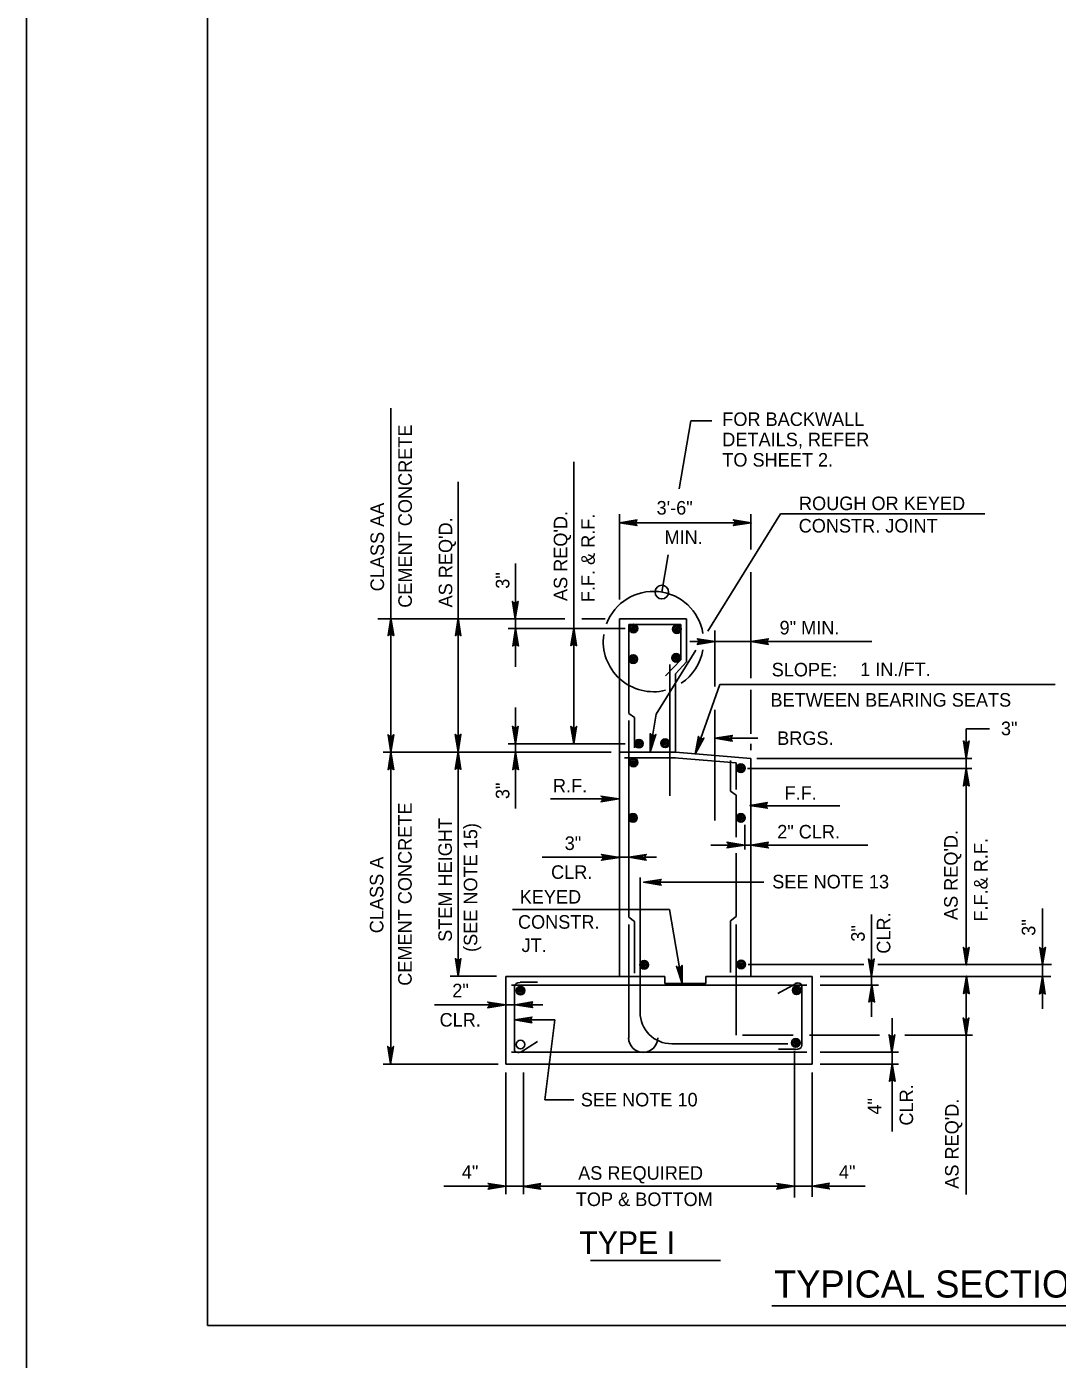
# Model space of a CAD drawing. Extents: x 235 to 2276, y 116 to 1308.
# Drawn here: x 579.4 to 807.5, y 717.9 to 1012.9 of the extents above; entities that cross this region are included whole.
import ezdxf

# ---------------------------------------------------------------- set-up
doc = ezdxf.new("R2010")
doc.units = 0
doc.layers.add('1', color=7, linetype='Continuous')
doc.layers.add('PLT-BNDY', color=7, linetype='Continuous')

msp = doc.modelspace()

# ---------------------------------------------------------------- linework, layer by layer
at = {"layer": '1'}
for p, q in [((619.42, 725.41), (619.42, 1289.41)), ((660.02, 879.66), (660.02, 928.45)), ((723.87, 910.62), (726.42, 925.68)), ((726.42, 925.68), (731.07, 925.68)), ((700.51, 916.6), (700.51, 889.19)), ((674.93, 879.66), (674.93, 912.13)), ((710.65, 886.09), (710.65, 904.97)), ((710.65, 903.1), (739.71, 903.1)), ((746.27, 905.11), (730.15, 879.09)), ((739.71, 897.2), (739.71, 904.97)), ((746.27, 905.11), (791.46, 905.11)), ((687.58, 881.85), (687.58, 894.1)), ((720, 887.75), (721.39, 895.99)), ((739.71, 868.72), (739.71, 892.15)), ((700.51, 889.19), (700.51, 877.63)), ((698.53, 881.85), (657.12, 881.85)), ((660.02, 852.32), (660.02, 881.85)), ((674.93, 802.76), (674.93, 881.85)), ((711.9, 879.66), (685.96, 879.66)), ((687.58, 881.85), (687.58, 871.22)), ((700.51, 879.66), (700.51, 854.19)), ((707.44, 881.85), (702.3, 881.85)), ((710.65, 802.63), (710.65, 881.85)), ((710.65, 881.85), (725.49, 881.85)), ((712.68, 860.91), (712.68, 880.6)), ((712.68, 880.6), (724.24, 880.6)), ((724.24, 872.79), (724.24, 880.6)), ((725.49, 872.32), (725.49, 881.85)), ((731.74, 866.88), (731.74, 879.23)), ((726.22, 876.8), (766.46, 876.8)), ((727.52, 874.86), (718.77, 860.76)), ((720.81, 869.19), (724.24, 872.79)), ((721.74, 842.63), (721.74, 871.69)), ((722.99, 869.66), (725.49, 872.32)), ((722.99, 852.32), (722.99, 869.66)), ((732.84, 867.31), (807.06, 867.31)), ((739.71, 865.13), (739.71, 866.1)), ((739.71, 856.4), (739.71, 865.13)), ((687.58, 854.19), (687.58, 862.21)), ((731.74, 837.16), (731.74, 861.72)), ((713.93, 859.97), (712.68, 860.91)), ((712.68, 815.76), (712.68, 859.35)), ((713.93, 853.26), (713.93, 859.97)), ((717.37, 852.32), (718.77, 860.76)), ((787.37, 848.72), (787.37, 857.45)), ((787.37, 857.45), (792.5, 857.45)), ((711.9, 854.19), (685.96, 854.19)), ((687.58, 854.19), (687.58, 839.87)), ((731.74, 855.38), (741.27, 855.38)), ((739.71, 852.79), (739.71, 854.18)), ((680.34, 852.32), (658.31, 852.32)), ((660.02, 852.32), (660.02, 783.26)), ((708.77, 852.32), (680.34, 852.32)), ((710.65, 852.32), (722.99, 852.32)), ((711.74, 851.07), (722.99, 851.07)), ((722.84, 851.07), (736.43, 849.97)), ((722.99, 852.32), (739.71, 850.91)), ((735.18, 843.72), (735.18, 850.44)), ((736.43, 844.04), (736.43, 849.97)), ((739.71, 802.63), (739.71, 850.91)), ((741, 850.91), (788.62, 850.91)), ((738.93, 848.72), (759.4, 848.72)), ((759.4, 848.72), (788.62, 848.72)), ((787.37, 805.29), (787.37, 848.72)), ((735.18, 843.72), (736.43, 842.79)), ((695.34, 842.01), (710.65, 842.01)), ((736.43, 833.52), (736.43, 842.79)), ((739.71, 840.44), (759.4, 840.44)), ((738.39, 830.75), (738.39, 836.22)), ((693.5, 829.04), (710.65, 829.04)), ((710.65, 829.04), (718.83, 829.04)), ((738.39, 831.74), (730.88, 831.74)), ((736.43, 815.91), (736.43, 829.99)), ((739.71, 831.74), (738.39, 831.74)), ((765.61, 831.74), (739.71, 831.74)), ((715.18, 794.77), (715.18, 824.61)), ((742.55, 823.54), (715.98, 823.54)), ((721.7, 817.47), (686.94, 817.47)), ((724.47, 801.1), (721.7, 817.47)), ((804.24, 805.29), (804.24, 817.73)), ((713.93, 814.82), (712.68, 815.76)), ((713.93, 803.41), (713.93, 814.82)), ((735.18, 814.97), (736.43, 815.91)), ((735.18, 803.57), (735.18, 814.97)), ((766.43, 802.63), (766.43, 816.36)), ((712.68, 789.04), (712.68, 814.19)), ((736.43, 789.66), (736.43, 814.19)), ((673.19, 802.76), (683.38, 802.76)), ((685.49, 783.26), (685.49, 802.63)), ((685.49, 802.63), (720.65, 802.63)), ((720.65, 802.63), (720.65, 801.1)), ((729.71, 802.63), (753.31, 802.63)), ((729.71, 802.63), (729.71, 801.1)), ((739.09, 805.29), (764.71, 805.29)), ((753.31, 783.26), (753.31, 802.63)), ((755.01, 802.63), (806.12, 802.63)), ((766.43, 793.72), (766.43, 802.63)), ((767.84, 805.29), (806.27, 805.29)), ((787.37, 789.66), (787.37, 802.63)), ((804.22, 795.48), (804.22, 805.29)), ((686.74, 800.76), (752.06, 800.76)), ((687.37, 800.6), (687.37, 786.38)), ((692.52, 801.38), (688.62, 801.38)), ((720.65, 801.1), (729.71, 801.1)), ((749.56, 801.07), (745.65, 798.88)), ((750.96, 787.32), (750.96, 800.76)), ((755.01, 800.76), (767.99, 800.76)), ((669.66, 796.39), (685.49, 796.39)), ((685.49, 796.39), (693.68, 796.39)), ((687.37, 793.07), (696.31, 793.07)), ((696.31, 793.07), (694.09, 775.33)), ((770.96, 785.91), (770.96, 793.41)), ((688.77, 785.91), (692.52, 788.26)), ((747.86, 787.77), (722.18, 787.77)), ((737.84, 789.66), (749.08, 789.66)), ((752.68, 789.66), (759.4, 789.66)), ((759.4, 789.66), (768.15, 789.66)), ((773.77, 789.66), (788.77, 789.66)), ((787.37, 754.43), (787.37, 789.66)), ((686.74, 785.91), (752.06, 785.91)), ((745.81, 786.54), (749.56, 786.54)), ((749.4, 786.22), (749.4, 753.72)), ((755.01, 785.91), (772.37, 785.91)), ((770.96, 768.33), (770.96, 785.91)), ((680.34, 783.26), (658.31, 783.26)), ((683.77, 783.26), (680.34, 783.26)), ((685.49, 783.26), (753.31, 783.26)), ((755.01, 783.26), (772.37, 783.26)), ((685.49, 781.38), (685.49, 776.38)), ((689.4, 781.38), (689.4, 754.51)), ((753.31, 781.38), (753.31, 776.38)), ((685.49, 776.38), (685.49, 754.51)), ((753.31, 776.38), (753.31, 753.88)), ((694.09, 775.33), (700.49, 775.33)), ((689.4, 756.22), (671.74, 756.22)), ((689.4, 756.22), (749.4, 756.22)), ((749.4, 756.22), (765.04, 756.22)), ((704.23, 739.79), (732.98, 739.79)), ((744.38, 729.75), (916.51, 729.75)), ((1405.42, 725.41), (619.42, 725.41))]:
    msp.add_line(p, q, dxfattribs=at)
for points in [[(714.4, 902.6), (714.27, 902.85), (710.65, 903.1), (714.4, 902.6), (714.52, 902.47), (710.65, 903.1), (714.27, 903.22), (714.4, 903.6), (710.65, 903.1), (714.52, 903.72), (714.4, 903.6)], [(736.05, 903.58), (736.18, 903.33), (739.8, 903.08), (736.05, 903.58), (735.8, 903.71), (739.8, 903.08), (736.18, 902.96), (736.05, 902.71), (739.8, 903.08), (735.8, 902.46), (736.05, 902.71)], [(688.07, 885.56), (687.82, 885.31), (687.57, 881.81), (688.07, 885.56), (688.19, 885.69), (687.57, 881.81), (687.44, 885.31), (687.19, 885.44), (687.57, 881.81), (686.94, 885.69), (687.19, 885.44)], [(659.52, 878.25), (659.77, 878.38), (660.02, 882), (659.52, 878.25), (659.4, 878.13), (660.02, 882), (660.15, 878.38), (660.52, 878.25), (660.02, 882), (660.65, 878.13), (660.52, 878.25)], [(674.42, 878.22), (674.67, 878.34), (674.92, 881.97), (674.42, 878.22), (674.3, 878.09), (674.92, 881.97), (675.05, 878.34), (675.42, 878.22), (674.92, 881.97), (675.55, 878.09), (675.42, 878.22)], [(687.13, 875.91), (687.38, 876.04), (687.63, 879.66), (687.13, 875.91), (687, 875.79), (687.63, 879.66), (687.75, 876.04), (688.13, 875.91), (687.63, 879.66), (688.25, 875.79), (688.13, 875.91)], [(700, 876.02), (700.25, 876.15), (700.5, 879.77), (700, 876.02), (699.87, 875.9), (700.5, 879.77), (700.62, 876.15), (701, 876.02), (700.5, 879.77), (701.12, 875.9), (701, 876.02)], [(728.08, 877.29), (728.21, 877.04), (731.83, 876.79), (728.08, 877.29), (727.83, 877.41), (731.83, 876.79), (728.21, 876.66), (728.08, 876.41), (731.83, 876.79), (727.83, 876.16), (728.08, 876.41)], [(743.46, 876.3), (743.34, 876.55), (739.71, 876.8), (743.46, 876.3), (743.59, 876.18), (739.71, 876.8), (743.34, 876.93), (743.46, 877.3), (739.71, 876.8), (743.59, 877.43), (743.46, 877.3)], [(732.84, 867.31), (727.37, 851.85)], [(660.52, 856.07), (660.27, 855.82), (660.02, 852.32), (660.52, 856.07), (660.65, 856.19), (660.02, 852.32), (659.9, 855.82), (659.65, 855.94), (660.02, 852.32), (659.4, 856.19), (659.65, 855.94)], [(675.4, 856.12), (675.15, 855.87), (674.9, 852.37), (675.4, 856.12), (675.52, 856.25), (674.9, 852.37), (674.77, 855.87), (674.52, 856), (674.9, 852.37), (674.27, 856.25), (674.52, 856)], [(688.08, 857.94), (687.83, 857.69), (687.58, 854.19), (688.08, 857.94), (688.2, 858.07), (687.58, 854.19), (687.45, 857.69), (687.2, 857.82), (687.58, 854.19), (686.95, 858.07), (687.2, 857.82)], [(701.01, 857.9), (700.76, 857.65), (700.51, 854.15), (701.01, 857.9), (701.14, 858.03), (700.51, 854.15), (700.39, 857.65), (700.14, 857.78), (700.51, 854.15), (699.89, 858.03), (700.14, 857.78)], [(718.5, 856.07), (718.2, 855.98), (717.41, 852.42), (718.5, 856.07), (718.69, 856.23), (717.41, 852.42), (717.83, 856.04), (717.58, 856.21), (717.41, 852.42), (717.44, 856.44), (717.58, 856.21)], [(729.08, 855.3), (728.78, 855.26), (727.37, 851.9), (729.08, 855.3), (729.3, 855.43), (727.37, 851.9), (728.42, 855.38), (728.21, 855.6), (727.37, 851.9), (728.1, 855.85), (728.21, 855.6)], [(735.48, 854.89), (735.35, 855.14), (731.73, 855.39), (735.48, 854.89), (735.6, 854.77), (731.73, 855.39), (735.35, 855.52), (735.48, 855.89), (731.73, 855.39), (735.6, 856.02), (735.48, 855.89)], [(787.87, 854.66), (787.62, 854.41), (787.37, 850.91), (787.87, 854.66), (787.99, 854.79), (787.37, 850.91), (787.24, 854.41), (786.99, 854.54), (787.37, 850.91), (786.74, 854.79), (786.99, 854.54)], [(659.52, 848.57), (659.77, 848.69), (660.02, 852.32), (659.52, 848.57), (659.4, 848.44), (660.02, 852.32), (660.15, 848.69), (660.52, 848.57), (660.02, 852.32), (660.65, 848.44), (660.52, 848.57)], [(674.4, 848.62), (674.65, 848.75), (674.9, 852.37), (674.4, 848.62), (674.27, 848.5), (674.9, 852.37), (675.02, 848.75), (675.4, 848.62), (674.9, 852.37), (675.52, 848.5), (675.4, 848.62)], [(687.13, 848.57), (687.38, 848.69), (687.63, 852.32), (687.13, 848.57), (687, 848.44), (687.63, 852.32), (687.75, 848.69), (688.13, 848.57), (687.63, 852.32), (688.25, 848.44), (688.13, 848.57)], [(786.87, 844.97), (787.12, 845.1), (787.37, 848.72), (786.87, 844.97), (786.74, 844.85), (787.37, 848.72), (787.49, 845.1), (787.87, 844.97), (787.37, 848.72), (787.99, 844.85), (787.87, 844.97)], [(706.76, 842.49), (706.88, 842.24), (710.51, 841.99), (706.76, 842.49), (706.51, 842.61), (710.51, 841.99), (706.88, 841.86), (706.76, 841.61), (710.51, 841.99), (706.51, 841.36), (706.76, 841.61)], [(743.25, 840.03), (743.13, 840.28), (739.5, 840.53), (743.25, 840.03), (743.38, 839.9), (739.5, 840.53), (743.13, 840.65), (743.25, 841.03), (739.5, 840.53), (743.38, 841.15), (743.25, 841.03)], [(734.64, 832.24), (734.76, 831.99), (738.39, 831.74), (734.64, 832.24), (734.39, 832.37), (738.39, 831.74), (734.76, 831.62), (734.64, 831.37), (738.39, 831.74), (734.39, 831.12), (734.64, 831.37)], [(743.46, 831.24), (743.34, 831.49), (739.71, 831.74), (743.46, 831.24), (743.59, 831.12), (739.71, 831.74), (743.34, 831.87), (743.46, 832.24), (739.71, 831.74), (743.59, 832.37), (743.46, 832.24)], [(706.88, 829.53), (707, 829.28), (710.63, 829.03), (706.88, 829.53), (706.63, 829.66), (710.63, 829.03), (707, 828.91), (706.88, 828.66), (710.63, 829.03), (706.63, 828.41), (706.88, 828.66)], [(716.42, 828.55), (716.3, 828.8), (712.67, 829.05), (716.42, 828.55), (716.55, 828.43), (712.67, 829.05), (716.3, 829.18), (716.42, 829.55), (712.67, 829.05), (716.55, 829.68), (716.42, 829.55)], [(719.73, 823.04), (719.61, 823.29), (715.98, 823.54), (719.73, 823.04), (719.86, 822.91), (715.98, 823.54), (719.61, 823.66), (719.73, 824.04), (715.98, 823.54), (719.86, 824.16), (719.73, 824.04)], [(787.88, 808.98), (787.63, 808.73), (787.38, 805.23), (787.88, 808.98), (788, 809.1), (787.38, 805.23), (787.25, 808.73), (787, 808.85), (787.38, 805.23), (786.75, 809.1), (787, 808.85)], [(804.76, 808.97), (804.51, 808.72), (804.26, 805.22), (804.76, 808.97), (804.89, 809.09), (804.26, 805.22), (804.14, 808.72), (803.89, 808.84), (804.26, 805.22), (803.64, 809.09), (803.89, 808.84)], [(675.43, 806.51), (675.18, 806.26), (674.93, 802.76), (675.43, 806.51), (675.55, 806.64), (674.93, 802.76), (674.8, 806.26), (674.55, 806.39), (674.93, 802.76), (674.3, 806.64), (674.55, 806.39)], [(766.87, 806.42), (766.62, 806.17), (766.37, 802.67), (766.87, 806.42), (767, 806.54), (766.37, 802.67), (766.25, 806.17), (766, 806.29), (766.37, 802.67), (765.75, 806.54), (766, 806.29)], [(724.36, 804.91), (724.11, 804.73), (724.47, 801.1), (724.36, 804.91), (724.49, 805.13), (724.47, 801.1), (723.74, 804.67), (723.45, 804.76), (724.47, 801.1), (723.24, 804.93), (723.45, 804.76)], [(786.9, 799), (787.15, 799.13), (787.4, 802.75), (786.9, 799), (786.78, 798.88), (787.4, 802.75), (787.53, 799.13), (787.9, 799), (787.4, 802.75), (788.03, 798.88), (787.9, 799)], [(803.74, 798.88), (803.99, 799.01), (804.24, 802.63), (803.74, 798.88), (803.62, 798.76), (804.24, 802.63), (804.37, 799.01), (804.74, 798.88), (804.24, 802.63), (804.87, 798.76), (804.74, 798.88)], [(765.95, 797.13), (766.2, 797.25), (766.45, 800.88), (765.95, 797.13), (765.83, 797), (766.45, 800.88), (766.58, 797.25), (766.95, 797.13), (766.45, 800.88), (767.08, 797), (766.95, 797.13)], [(681.72, 796.89), (681.85, 796.64), (685.47, 796.39), (681.72, 796.89), (681.47, 797.01), (685.47, 796.39), (681.85, 796.26), (681.72, 796.01), (685.47, 796.39), (681.47, 795.76), (681.72, 796.01)], [(691.27, 795.91), (691.14, 796.16), (687.52, 796.41), (691.27, 795.91), (691.39, 795.78), (687.52, 796.41), (691.14, 796.53), (691.27, 796.91), (687.52, 796.41), (691.39, 797.03), (691.27, 796.91)], [(691.12, 792.57), (690.99, 792.82), (687.37, 793.07), (691.12, 792.57), (691.24, 792.44), (687.37, 793.07), (690.99, 793.19), (691.12, 793.57), (687.37, 793.07), (691.24, 793.69), (691.12, 793.57)], [(787.83, 793.37), (787.58, 793.12), (787.33, 789.62), (787.83, 793.37), (787.95, 793.49), (787.33, 789.62), (787.2, 793.12), (786.95, 793.24), (787.33, 789.62), (786.7, 793.49), (786.95, 793.24)], [(771.43, 789.62), (771.18, 789.37), (770.93, 785.87), (771.43, 789.62), (771.55, 789.75), (770.93, 785.87), (770.8, 789.37), (770.55, 789.5), (770.93, 785.87), (770.3, 789.75), (770.55, 789.5)], [(660.48, 787.05), (660.23, 786.8), (659.98, 783.3), (660.48, 787.05), (660.6, 787.17), (659.98, 783.3), (659.85, 786.8), (659.6, 786.92), (659.98, 783.3), (659.35, 787.17), (659.6, 786.92)], [(770.49, 779.6), (770.74, 779.73), (770.99, 783.35), (770.49, 779.6), (770.37, 779.48), (770.99, 783.35), (771.12, 779.73), (771.49, 779.6), (770.99, 783.35), (771.62, 779.48), (771.49, 779.6)], [(681.79, 756.72), (681.92, 756.47), (685.54, 756.22), (681.79, 756.72), (681.54, 756.85), (685.54, 756.22), (681.92, 756.1), (681.79, 755.85), (685.54, 756.22), (681.54, 755.6), (681.79, 755.85)], [(693.08, 755.71), (692.95, 755.96), (689.33, 756.21), (693.08, 755.71), (693.2, 755.58), (689.33, 756.21), (692.95, 756.33), (693.08, 756.71), (689.33, 756.21), (693.2, 756.83), (693.08, 756.71)], [(745.64, 756.74), (745.76, 756.49), (749.39, 756.24), (745.64, 756.74), (745.39, 756.87), (749.39, 756.24), (745.76, 756.12), (745.64, 755.87), (749.39, 756.24), (745.39, 755.62), (745.64, 755.87)], [(756.99, 755.75), (756.86, 756), (753.24, 756.25), (756.99, 755.75), (757.11, 755.63), (753.24, 756.25), (756.86, 756.38), (756.99, 756.75), (753.24, 756.25), (757.11, 756.88), (756.99, 756.75)]]:
    msp.add_lwpolyline(points, dxfattribs=at)
for centre, radius in [((720, 887.75), 1.51), ((713.71, 879.71), 0.954), ((713.71, 879.71), 0.681), ((713.71, 879.71), 0.372), ((713.71, 879.71), 0.188), ((713.71, 879.71), 0.0805), ((723.3, 879.57), 0.954), ((723.3, 879.57), 0.681), ((723.3, 879.57), 0.372), ((723.3, 879.57), 0.188), ((723.3, 879.57), 0.0805), ((713.69, 872.93), 0.954), ((713.69, 872.93), 0.681), ((713.69, 872.93), 0.372), ((723.17, 873.18), 0.954), ((723.17, 873.18), 0.681), ((723.17, 873.18), 0.372), ((723.17, 873.18), 0.188), ((723.17, 873.18), 0.0805), ((713.69, 872.93), 0.188), ((713.69, 872.93), 0.0805), ((714.92, 854.2), 0.954), ((714.92, 854.2), 0.681), ((714.92, 854.2), 0.372), ((714.92, 854.2), 0.188), ((714.92, 854.2), 0.0805), ((720.74, 854.28), 0.954), ((720.74, 854.28), 0.681), ((720.74, 854.28), 0.372), ((720.74, 854.28), 0.188), ((720.74, 854.28), 0.0805), ((713.73, 850.06), 0.954), ((713.73, 850.06), 0.681), ((713.73, 850.06), 0.372), ((713.73, 850.06), 0.188), ((713.73, 850.06), 0.0805), ((737.49, 848.77), 0.954), ((737.49, 848.77), 0.681), ((737.49, 848.77), 0.372), ((737.49, 848.77), 0.188), ((737.49, 848.77), 0.0805), ((713.62, 837.77), 0.954), ((713.62, 837.77), 0.681), ((713.62, 837.77), 0.372), ((713.62, 837.77), 0.188), ((713.62, 837.77), 0.0805), ((737.5, 837.76), 0.954), ((737.5, 837.76), 0.681), ((737.5, 837.76), 0.372), ((737.5, 837.76), 0.188), ((737.5, 837.76), 0.0805), ((716.11, 805.25), 0.954), ((716.11, 805.25), 0.681), ((716.11, 805.25), 0.372), ((716.11, 805.25), 0.188), ((737.56, 805.34), 0.954), ((737.56, 805.34), 0.681), ((737.56, 805.34), 0.372), ((737.56, 805.34), 0.188), ((737.56, 805.34), 0.0805), ((716.11, 805.25), 0.0805), ((688.72, 799.53), 0.954), ((688.72, 799.53), 0.681), ((688.72, 799.53), 0.372), ((688.72, 799.53), 0.188), ((688.72, 799.53), 0.0805), ((749.84, 799.62), 0.954), ((749.84, 799.62), 0.681), ((749.84, 799.62), 0.372), ((749.84, 799.62), 0.188), ((749.84, 799.62), 0.0805), ((688.72, 787.59), 0.954), ((749.63, 787.97), 0.954), ((749.63, 787.97), 0.681), ((749.63, 787.97), 0.372), ((749.63, 787.97), 0.188), ((749.63, 787.97), 0.0805)]:
    msp.add_circle(centre, radius, dxfattribs=at)
for centre, radius, start, end in [((718.14, 876.8), 11.11, 9.2933, 159.1932), ((718.14, 876.8), 11.11, 172.0304, 284.0362), ((718.14, 876.8), 11.11, 303.6901, 350.7067), ((722.18, 794.77), 7, 180, 270), ((715.86, 789.09), 3.22, 180, 0)]:
    msp.add_arc(centre, radius, start, end, dxfattribs=at)
for centre, major_axis, ratio, start_param, end_param in [((688.67, 800.53), (-1.3, 0), 0.602565, 4.712389, 6.283185), ((750.12, 800.76), (-0.812, 0), 0.572437, 3.141593, 5.497787), ((688.18, 786.33), (0.812, 0), 0.602565, 3.141593, 5.497787), ((749.63, 787.27), (1.3, 0), 0.572437, 4.712389, 6.283185)]:
    msp.add_ellipse(centre, major_axis=major_axis, ratio=ratio, start_param=start_param, end_param=end_param, dxfattribs=at)
at = {"layer": 'PLT-BNDY'}
msp.add_lwpolyline([(579.42, 1304.41), (1420.42, 1304.41), (1420.42, 710.41), (579.42, 710.41)], close=True, dxfattribs=at)

# ---------------------------------------------------------------- texts
at = {"layer": '1'}
for s, height, p in [('FOR BACKWALL', 3, (733.38, 924.53)), ('DETAILS, REFER', 3, (733.38, 920.03)), ('TO SHEET 2.', 3, (733.38, 915.53)), ('ROUGH OR KEYED', 3, (750.35, 905.89)), ('3\'-6"', 3.003, (718.84, 904.91)), ('CONSTR. JOINT', 3, (750.29, 900.94)), ('MIN.', 3, (720.6, 898.39)), ('9" MIN.', 3.003, (746.06, 878.38)), ('SLOPE:', 3, (744.32, 869.09)), ('1 IN./FT.', 3.003, (763.89, 869.15)), ('BETWEEN BEARING SEATS', 3, (744.04, 862.39)), ('3"', 3.003, (795.05, 856.08)), ('  BRGS.', 3, (743.3, 853.92)), ('R.F.', 3, (695.9, 843.39)), ('F.F.', 3, (747.17, 841.77)), ('2" CLR.', 3, (745.54, 833.21)), ('3"', 3.003, (698.5, 830.66)), ('CLR.', 3, (695.49, 824.27)), ('SEE NOTE 13', 3, (744.44, 822.16)), ('KEYED ', 3, (688.54, 818.79)), ('CONSTR. ', 3, (688.16, 813.24)), ('JT.', 3, (688.95, 808.08)), ('2"', 3.003, (673.62, 798.05)), ('CLR.', 3, (670.81, 791.57)), ('SEE NOTE 10', 3, (702.06, 773.9)), ('4"', 3.003, (675.74, 757.89)), (' AS REQUIRED ', 3, (700.37, 757.67)), ('4"', 3.003, (759.2, 757.89)), ('TOP & BOTTOM', 3, (700.96, 751.85)), (' TYPE I', 5, (699.87, 741.25)), ('TYPICAL SECTION WITH BACKWALL', 6, (744.85, 731.59))]:
    msp.add_text(s, height=height, dxfattribs=at).set_placement(p)
for s, p in [('CEMENT CONCRETE', (664.68, 884.28)), ('CLASS AA', (658.52, 887.92)), ("AS REQ'D.", (673.62, 884.36)), ("AS REQ'D.", (699.08, 885.77)), ('F.F. & R.F.', (705.17, 885.51)), ('3"', (686.26, 888.49)), ('3"', (686.26, 841.93)), ('CEMENT CONCRETE', (664.64, 800.61)), ('STEM HEIGHT', (673.54, 810.33)), ('(SEE NOTE 15)', (679.16, 808.09)), ("AS REQ'D.", (785.48, 815.16)), ('F.F.& R.F.', (792.09, 814.81)), ('CLASS A', (658.38, 812.24)), ('CLR.', (770.58, 807.71)), ('3"', (802.67, 811.68)), ('3"', (764.91, 810.36)), ('CLR.', (775.62, 769.67)), ('4"', (768.58, 772.1)), ("AS REQ'D.", (785.69, 755.68))]:
    msp.add_text(s, height=3, rotation=90, dxfattribs=at).set_placement(p)

doc.saveas('drawing.dxf')
